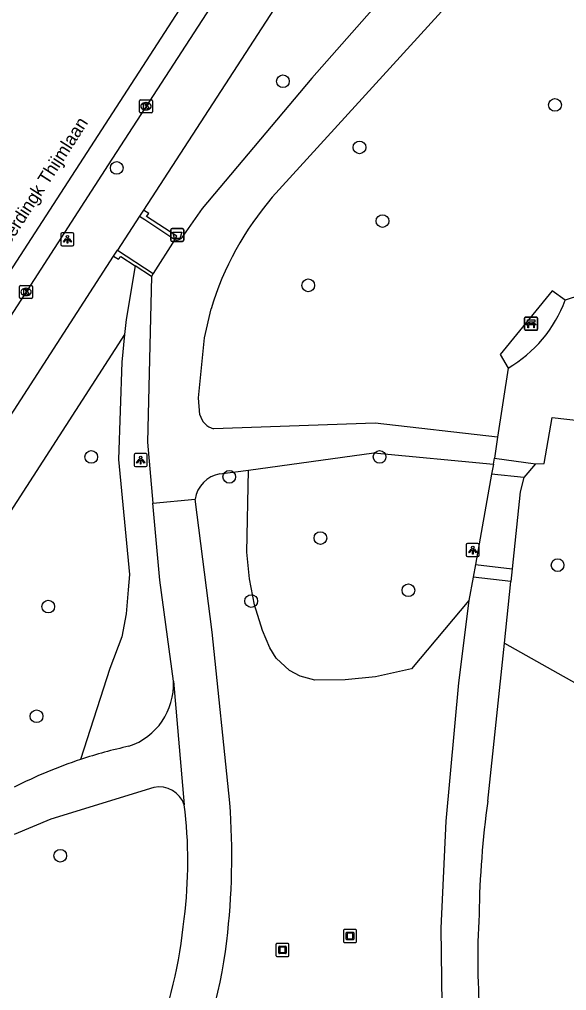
# Model space of a CAD drawing. Extents: x 161402 to 161933, y 381650 to 382313.
# Drawn here: x 161500.4 to 161542.5, y 381916.2 to 381991 of the extents above; entities that cross this region are included whole.
import ezdxf

# ---------------------------------------------------------------- set-up
doc = ezdxf.new("R2010")
doc.units = 0
for name, color, linetype in [('IMGEO_Afvalbak', 7, 'Continuous'), ('IMGEO_Bank', 7, 'Continuous'), ('IMGEO_Boom', 7, 'Continuous'), ('IMGEO_Groenvoorziening', 7, 'Continuous'), ('IMGEO_Kolk', 7, 'Continuous'), ('IMGEO_Kunstobject', 7, 'Continuous'), ('IMGEO_Lichtpunt', 7, 'Continuous'), ('IMGEO_Muur', 7, 'Continuous'), ('IMGEO_Openbare_ruimte_label', 7, 'Continuous'), ('IMGEO_Rijbaan_lokaal_gesloten', 7, 'Continuous'), ('IMGEO_Voetpad_gesloten', 7, 'Continuous'), ('IMGEO_Voetpad_open', 7, 'Continuous')]:
    doc.layers.add(name, color=color, linetype=linetype)

msp = doc.modelspace()

# ---------------------------------------------------------------- linework, layer by layer
at = {"layer": 'IMGEO_Afvalbak'}
for p, q in [((161512.056, 381973.98), (161512.056, 381974.78)), ((161512.056, 381974.78), (161512.056, 381973.98)), ((161512.156, 381974.88), (161512.946, 381974.88)), ((161512.946, 381974.88), (161512.156, 381974.88)), ((161513.046, 381974.78), (161513.046, 381973.98)), ((161513.046, 381973.98), (161513.046, 381974.78)), ((161512.946, 381973.88), (161512.156, 381973.88)), ((161512.156, 381973.88), (161512.946, 381973.88))]:
    msp.add_line(p, q, dxfattribs=at)
msp.add_lwpolyline([(161512.199, 381974.594), (161512.903, 381974.594), (161512.754, 381974.124), (161512.348, 381974.124), (161512.199, 381974.594)], dxfattribs=at)
for centre, start, end in [((161512.156, 381974.78), 90, 180), ((161512.156, 381974.78), 90, 180), ((161512.946, 381974.78), 0, 90), ((161512.946, 381974.78), 360, 90), ((161512.156, 381973.98), 180, 270), ((161512.156, 381973.98), 180, 270), ((161512.946, 381973.98), 270, 0), ((161512.946, 381973.98), 270, 0)]:
    msp.add_arc(centre, 0.1, start, end, dxfattribs=at)
at = {"layer": 'IMGEO_Bank'}
for p, q in [((161539.283, 381967.136), (161539.283, 381967.977)), ((161539.283, 381967.977), (161539.283, 381967.136)), ((161539.358, 381968.061), (161540.199, 381968.061)), ((161540.199, 381968.061), (161539.358, 381968.061)), ((161540.283, 381967.986), (161540.283, 381967.145)), ((161540.283, 381967.145), (161540.283, 381967.986)), ((161540.208, 381967.061), (161539.367, 381967.061)), ((161539.367, 381967.061), (161540.208, 381967.061)), ((161539.98, 381967.459), (161539.587, 381967.459)), ((161539.592, 381967.567), (161539.592, 381967.673)), ((161539.636, 381967.673), (161539.636, 381967.567)), ((161539.924, 381967.679), (161539.642, 381967.679)), ((161539.642, 381967.561), (161539.924, 381967.561)), ((161539.93, 381967.567), (161539.93, 381967.673)), ((161539.974, 381967.673), (161539.974, 381967.567))]:
    msp.add_line(p, q, dxfattribs=at)
for points in [[(161539.586, 381967.679), (161539.5, 381967.679), (161539.5, 381967.84), (161540.063, 381967.84), (161540.063, 381967.679), (161539.98, 381967.679)], [(161539.53, 381967.459), (161539.388, 381967.459), (161539.5, 381967.561), (161539.586, 381967.561)], [(161539.58, 381967.452), (161539.58, 381967.245), (161539.537, 381967.245), (161539.537, 381967.452)], [(161539.98, 381967.561), (161540.063, 381967.561), (161540.175, 381967.459), (161540.036, 381967.459)], [(161540.03, 381967.452), (161540.03, 381967.245), (161539.986, 381967.245), (161539.986, 381967.452)]]:
    msp.add_lwpolyline(points, dxfattribs=at)
for centre, radius, start, end in [((161539.361, 381967.983), 0.0779, 92.4484, 184.28452), ((161539.361, 381967.983), 0.0779, 92.4484, 184.28452), ((161540.205, 381967.983), 0.0779, 2.4484, 94.28452), ((161540.205, 381967.983), 0.0779, 2.4484, 94.28452), ((161539.361, 381967.139), 0.0779, 182.4484, 274.28452), ((161539.361, 381967.139), 0.0779, 182.4484, 274.28452), ((161539.53, 381967.452), 0.00671, 2.89567, 87.10433), ((161539.587, 381967.452), 0.00671, 92.89567, 177.10433), ((161539.585, 381967.672), 0.00671, 2.89567, 87.10433), ((161539.585, 381967.568), 0.00671, 272.89567, 357.10433), ((161539.642, 381967.672), 0.00671, 92.89567, 177.10433), ((161539.642, 381967.568), 0.00671, 182.89567, 267.10433), ((161539.924, 381967.672), 0.00671, 2.89567, 87.10433), ((161539.924, 381967.568), 0.00671, 272.89567, 357.10433), ((161539.981, 381967.672), 0.00671, 92.89567, 177.10433), ((161539.981, 381967.568), 0.00671, 182.89567, 267.10433), ((161539.979, 381967.452), 0.00671, 2.89567, 87.10433), ((161540.036, 381967.452), 0.00671, 92.89567, 177.10433), ((161540.205, 381967.139), 0.0779, 272.4484, 4.28452), ((161540.205, 381967.139), 0.0779, 272.4484, 4.28452)]:
    msp.add_arc(centre, radius, start, end, dxfattribs=at)
at = {"layer": 'IMGEO_Boom'}
for centre in [(161520.681, 381986.224), (161541.622, 381984.404), (161526.576, 381981.129), (161507.896, 381979.545), (161528.346, 381975.453), (161522.628, 381970.508), (161505.933, 381957.295), (161528.12, 381957.302), (161516.555, 381955.763), (161523.568, 381951.047), (161541.817, 381948.963), (161530.341, 381947.03), (161502.618, 381945.772), (161518.24, 381946.2), (161501.719, 381937.331), (161503.545, 381926.59)]:
    msp.add_circle(centre, 0.489, dxfattribs=at)
at = {"layer": 'IMGEO_Groenvoorziening'}
for points in [[(161509.308, 381972.015), (161508.618, 381967.87), (161508.501, 381966.732)], [(161508.501, 381966.732), (161469.767, 381906.69), (161463.799, 381897.019)], [(161508.501, 381966.732), (161508.281, 381964.587), (161508.029, 381957.094), (161508.87, 381948.254), (161508.777, 381947.074), (161508.622, 381945.207), (161508.281, 381943.455), (161507.356, 381941.013), (161505.105, 381933.996)], [(161534.991, 381946.237), (161530.572, 381940.988), (161527.811, 381940.367), (161525.479, 381940.12), (161523.133, 381940.118), (161522.019, 381940.405), (161521.193, 381940.842), (161520.168, 381941.793), (161519.671, 381942.584), (161519.118, 381943.929), (161518.506, 381945.898), (161518.104, 381947.92), (161517.916, 381949.973), (161518.029, 381956.285)], [(161537.726, 381942.964), (161546.992, 381937.737), (161549.718, 381935.374), (161552.345, 381934.301)]]:
    msp.add_lwpolyline(points, dxfattribs=at)
at = {"layer": 'IMGEO_Kolk'}
for p, q in [((161509.644, 381983.873), (161509.644, 381984.725)), ((161509.719, 381984.799), (161510.571, 381984.799)), ((161510.132, 381984.579), (161510.157, 381984.579)), ((161510.645, 381984.725), (161510.645, 381983.873)), ((161510.571, 381983.799), (161509.719, 381983.799)), ((161510.155, 381984.019), (161510.13, 381984.019)), ((161500.415, 381969.577), (161500.415, 381970.429)), ((161500.49, 381970.503), (161501.342, 381970.503)), ((161500.903, 381970.283), (161500.928, 381970.283)), ((161501.416, 381970.429), (161501.416, 381969.577)), ((161501.342, 381969.503), (161500.49, 381969.503)), ((161500.926, 381969.723), (161500.901, 381969.723))]:
    msp.add_line(p, q, dxfattribs=at)
for points in [[(161509.644, 381983.873), (161509.644, 381984.725)], [(161509.719, 381984.799), (161510.571, 381984.799)], [(161509.965, 381984.499), (161510.088, 381984.499), (161510.088, 381984.348), (161510.218, 381984.499), (161510.382, 381984.499), (161510.236, 381984.348), (161510.389, 381984.099), (161510.237, 381984.099), (161510.152, 381984.263), (161510.088, 381984.196), (161510.088, 381984.099), (161509.965, 381984.099), (161509.965, 381984.499)], [(161510.645, 381984.725), (161510.645, 381983.873)], [(161510.571, 381983.799), (161509.719, 381983.799)], [(161500.415, 381969.577), (161500.415, 381970.429)], [(161500.49, 381970.503), (161501.342, 381970.503)], [(161500.736, 381970.203), (161500.859, 381970.203), (161500.859, 381970.052), (161500.989, 381970.203), (161501.153, 381970.203), (161501.007, 381970.052), (161501.16, 381969.803), (161501.008, 381969.803), (161500.923, 381969.967), (161500.859, 381969.9), (161500.859, 381969.803), (161500.736, 381969.803), (161500.736, 381970.203)], [(161501.416, 381970.429), (161501.416, 381969.577)], [(161501.342, 381969.503), (161500.49, 381969.503)]]:
    msp.add_lwpolyline(points, dxfattribs=at)
for centre, start, end in [((161509.721, 381984.723), 91.55205, 178.44795), ((161509.721, 381984.723), 91.55205, 178.44795), ((161510.569, 381984.723), 1.55205, 88.44795), ((161510.569, 381984.723), 1.55205, 88.44795), ((161509.721, 381983.875), 181.55205, 268.44795), ((161509.721, 381983.875), 181.55205, 268.44795), ((161510.569, 381983.875), 271.55205, 358.44795), ((161510.569, 381983.875), 271.55205, 358.44795), ((161500.492, 381970.427), 91.55205, 178.44795), ((161500.492, 381970.427), 91.55205, 178.44795), ((161501.34, 381970.427), 1.55205, 88.44795), ((161501.34, 381970.427), 1.55205, 88.44795), ((161500.492, 381969.579), 181.55205, 268.44795), ((161500.492, 381969.579), 181.55205, 268.44795), ((161501.34, 381969.579), 271.55205, 358.44795), ((161501.34, 381969.579), 271.55205, 358.44795)]:
    msp.add_arc(centre, 0.0765, start, end, dxfattribs=at)
for centre, major_axis, ratio, start_param, end_param in [((161510.131, 381984.299), (-0.387, 0.002), 0.722429, 4.712389, 7.853982), ((161510.156, 381984.299), (-0.39, 0.002), 0.717154, 1.570796, 4.712389), ((161500.902, 381970.003), (-0.387, 0.002), 0.722429, 4.712389, 7.853982), ((161500.927, 381970.003), (-0.39, 0.002), 0.717154, 1.570796, 4.712389)]:
    msp.add_ellipse(centre, major_axis=major_axis, ratio=ratio, start_param=start_param, end_param=end_param, dxfattribs=at)
at = {"layer": 'IMGEO_Kunstobject'}
for p, q in [((161525.344, 381920.824), (161525.344, 381919.983)), ((161525.344, 381920.824), (161525.344, 381919.983)), ((161526.26, 381920.908), (161525.419, 381920.908)), ((161526.26, 381920.908), (161525.419, 381920.908)), ((161525.608, 381920.696), (161526.082, 381920.696)), ((161526.344, 381919.992), (161526.344, 381920.833)), ((161526.344, 381919.992), (161526.344, 381920.833)), ((161525.558, 381920.172), (161525.558, 381920.646)), ((161526.082, 381920.122), (161525.608, 381920.122)), ((161525.638, 381920.596), (161525.638, 381920.222)), ((161526.032, 381920.616), (161525.658, 381920.616)), ((161525.658, 381920.202), (161526.032, 381920.202)), ((161526.052, 381920.222), (161526.052, 381920.596)), ((161526.132, 381920.646), (161526.132, 381920.172)), ((161520.149, 381919.753), (161520.149, 381918.912)), ((161520.149, 381919.753), (161520.149, 381918.912)), ((161521.065, 381919.837), (161520.224, 381919.837)), ((161521.065, 381919.837), (161520.224, 381919.837)), ((161520.363, 381919.101), (161520.363, 381919.575)), ((161520.413, 381919.625), (161520.887, 381919.625)), ((161520.443, 381919.525), (161520.443, 381919.151)), ((161520.837, 381919.545), (161520.463, 381919.545)), ((161520.857, 381919.151), (161520.857, 381919.525)), ((161520.937, 381919.575), (161520.937, 381919.101)), ((161521.149, 381918.921), (161521.149, 381919.762)), ((161521.149, 381918.921), (161521.149, 381919.762)), ((161525.428, 381919.908), (161526.269, 381919.908)), ((161525.428, 381919.908), (161526.269, 381919.908)), ((161520.233, 381918.837), (161521.074, 381918.837)), ((161520.233, 381918.837), (161521.074, 381918.837)), ((161520.887, 381919.051), (161520.413, 381919.051)), ((161520.463, 381919.131), (161520.837, 381919.131))]:
    msp.add_line(p, q, dxfattribs=at)
for centre, radius, start, end in [((161525.422, 381920.83), 0.0779, 92.4484, 184.28452), ((161525.422, 381920.83), 0.0779, 92.4484, 184.28452), ((161525.608, 381920.646), 0.05, 90, 180), ((161526.082, 381920.646), 0.05, 360, 90), ((161526.266, 381920.83), 0.0779, 2.4484, 94.28452), ((161526.266, 381920.83), 0.0779, 2.4484, 94.28452), ((161525.422, 381919.986), 0.0779, 182.4484, 274.28452), ((161525.422, 381919.986), 0.0779, 182.4484, 274.28452), ((161525.608, 381920.172), 0.05, 180, 270), ((161525.658, 381920.596), 0.02, 90, 180), ((161525.658, 381920.222), 0.02, 180, 270), ((161526.032, 381920.596), 0.02, 360, 90), ((161526.032, 381920.222), 0.02, 270, 0), ((161526.082, 381920.172), 0.05, 270, 0), ((161526.266, 381919.986), 0.0779, 272.4484, 4.28452), ((161526.266, 381919.986), 0.0779, 272.4484, 4.28452), ((161520.227, 381919.759), 0.0779, 92.4484, 184.28452), ((161520.227, 381919.759), 0.0779, 92.4484, 184.28452), ((161520.413, 381919.575), 0.05, 90, 180), ((161520.463, 381919.525), 0.02, 90, 180), ((161520.837, 381919.525), 0.02, 360, 90), ((161520.887, 381919.575), 0.05, 360, 90), ((161521.071, 381919.759), 0.0779, 2.4484, 94.28452), ((161521.071, 381919.759), 0.0779, 2.4484, 94.28452), ((161520.227, 381918.915), 0.0779, 182.4484, 274.28452), ((161520.227, 381918.915), 0.0779, 182.4484, 274.28452), ((161520.413, 381919.101), 0.05, 180, 270), ((161520.463, 381919.151), 0.02, 180, 270), ((161520.837, 381919.151), 0.02, 270, 0), ((161520.887, 381919.101), 0.05, 270, 0), ((161521.071, 381918.915), 0.0779, 272.4484, 4.28452), ((161521.071, 381918.915), 0.0779, 272.4484, 4.28452)]:
    msp.add_arc(centre, radius, start, end, dxfattribs=at)
at = {"layer": 'IMGEO_Lichtpunt'}
for p, q in [((161504.5, 381974.55), (161503.692, 381974.55)), ((161504.5, 381974.55), (161503.692, 381974.55)), ((161503.598, 381974.455), (161503.598, 381973.648)), ((161503.598, 381974.455), (161503.598, 381973.648)), ((161504.594, 381973.648), (161504.594, 381974.455)), ((161504.594, 381973.648), (161504.594, 381974.455)), ((161503.692, 381973.554), (161504.5, 381973.554)), ((161503.692, 381973.554), (161504.5, 381973.554)), ((161509.237, 381957.453), (161509.237, 381956.646)), ((161509.237, 381957.453), (161509.237, 381956.646)), ((161510.139, 381957.548), (161509.331, 381957.548)), ((161510.139, 381957.548), (161509.331, 381957.548)), ((161510.233, 381956.646), (161510.233, 381957.453)), ((161510.233, 381956.646), (161510.233, 381957.453)), ((161509.331, 381956.552), (161510.139, 381956.552)), ((161509.331, 381956.552), (161510.139, 381956.552)), ((161535.693, 381950.622), (161534.885, 381950.622)), ((161535.693, 381950.622), (161534.885, 381950.622)), ((161534.791, 381950.527), (161534.791, 381949.72)), ((161534.791, 381950.527), (161534.791, 381949.72)), ((161535.787, 381949.72), (161535.787, 381950.527)), ((161535.787, 381949.72), (161535.787, 381950.527)), ((161534.885, 381949.626), (161535.693, 381949.626)), ((161534.885, 381949.626), (161535.693, 381949.626))]:
    msp.add_line(p, q, dxfattribs=at)
for points in [[(161503.972, 381974.119), (161504.011, 381974.091), (161503.823, 381973.829), (161503.785, 381973.856), (161503.972, 381974.119)], [(161504.074, 381974.071), (161504.121, 381974.071), (161504.121, 381973.749), (161504.074, 381973.749), (161504.074, 381974.071)], [(161504.184, 381974.091), (161504.222, 381974.118), (161504.409, 381973.856), (161504.37, 381973.828), (161504.184, 381974.091)], [(161509.611, 381957.117), (161509.65, 381957.089), (161509.462, 381956.827), (161509.424, 381956.854), (161509.611, 381957.117)], [(161509.713, 381957.069), (161509.76, 381957.069), (161509.76, 381956.747), (161509.713, 381956.747), (161509.713, 381957.069)], [(161509.823, 381957.089), (161509.861, 381957.116), (161510.048, 381956.854), (161510.009, 381956.826), (161509.823, 381957.089)], [(161535.165, 381950.191), (161535.204, 381950.163), (161535.016, 381949.901), (161534.978, 381949.928), (161535.165, 381950.191)], [(161535.267, 381950.143), (161535.314, 381950.143), (161535.314, 381949.821), (161535.267, 381949.821), (161535.267, 381950.143)], [(161535.377, 381950.163), (161535.415, 381950.19), (161535.602, 381949.928), (161535.563, 381949.9), (161535.377, 381950.163)]]:
    msp.add_lwpolyline(points, dxfattribs=at)
for centre in [(161504.097, 381974.253), (161509.736, 381957.251), (161535.29, 381950.325)]:
    msp.add_circle(centre, 0.0994, dxfattribs=at)
for centre, start, end in [((161503.692, 381974.455), 90, 180), ((161503.692, 381974.455), 90, 180), ((161504.5, 381974.455), 0, 90), ((161504.5, 381974.455), 0, 90), ((161503.692, 381973.648), 180, 270), ((161503.692, 381973.648), 180, 270), ((161504.5, 381973.648), 270, 0), ((161504.5, 381973.648), 270, 360), ((161509.331, 381957.453), 90, 180), ((161509.331, 381957.453), 90, 180), ((161510.139, 381957.453), 0, 90), ((161510.139, 381957.453), 0, 90), ((161509.331, 381956.646), 180, 270), ((161509.331, 381956.646), 180, 270), ((161510.139, 381956.646), 270, 0), ((161510.139, 381956.646), 270, 360), ((161534.885, 381950.527), 90, 180), ((161534.885, 381950.527), 90, 180), ((161535.693, 381950.527), 0, 90), ((161535.693, 381950.527), 0, 90), ((161534.885, 381949.72), 180, 270), ((161534.885, 381949.72), 180, 270), ((161535.693, 381949.72), 270, 0), ((161535.693, 381949.72), 270, 360)]:
    msp.add_arc(centre, 0.0946, start, end, dxfattribs=at)
at = {"layer": 'IMGEO_Muur'}
for points in [[(161509.956, 381976.304), (161509.806, 381976.073), (161509.648, 381975.83)], [(161512.354, 381974.043), (161512.522, 381974.297), (161510.195, 381975.805), (161510.352, 381976.047), (161509.956, 381976.304)], [(161509.648, 381975.83), (161510.055, 381975.566), (161512.354, 381974.043)], [(161507.649, 381972.745), (161507.953, 381973.214)], [(161507.953, 381973.214), (161510.709, 381971.428)], [(161507.649, 381972.745), (161508.017, 381972.531), (161508.198, 381972.739), (161509.308, 381972.015)], [(161510.563, 381971.196), (161509.308, 381972.015)], [(161510.709, 381971.428), (161510.563, 381971.196)]]:
    msp.add_lwpolyline(points, dxfattribs=at)
at = {"layer": 'IMGEO_Rijbaan_lokaal_gesloten'}
for points in [[(161497.581, 381968.358), (161530.425, 382019.12)], [(161532.049, 382018.061), (161507.226, 381979.8), (161499.199, 381967.336)]]:
    msp.add_lwpolyline(points, dxfattribs=at)
at = {"layer": 'IMGEO_Voetpad_gesloten'}
for points in [[(161566.397, 382035.429), (161550.139, 382016.903), (161534.836, 382000), (161522.917, 381986.45), (161514.478, 381976.419), (161513.027, 381974.379)], [(161519.862, 381977.295), (161539.026, 381998.34)], [(161512.354, 381974.043), (161510.709, 381971.428)], [(161510.563, 381971.196), (161510.253, 381958.443), (161510.676, 381953.741)], [(161547.271, 381970.949), (161542.413, 381969.37)], [(161540.125, 381956.77), (161540.786, 381956.788), (161541.397, 381960.342), (161546.372, 381959.762), (161548.185, 381962.019), (161546.989, 381965.845), (161550.378, 381967.202), (161550.41, 381969.161), (161551.511, 381969.577)], [(161514.294, 381960.547), (161514.174, 381961.84), (161514.646, 381966.471), (161515.15, 381968.709)], [(161538.012, 381964.131), (161537.2, 381958.819)], [(161537.2, 381958.819), (161527.77, 381959.887), (161515.352, 381959.463)], [(161537.2, 381958.819), (161536.954, 381957.199)], [(161518.029, 381956.285), (161527.675, 381957.619), (161536.884, 381956.742)], [(161536.884, 381956.742), (161536.954, 381957.199)], [(161536.954, 381957.199), (161540.125, 381956.77)], [(161515.84, 381955.982), (161518.029, 381956.285)], [(161510.676, 381953.741), (161513.937, 381954.035)], [(161512.254, 381940.023), (161511.211, 381947.806), (161510.676, 381953.741)], [(161516.591, 381930.663), (161515.234, 381943.813), (161513.937, 381954.035)], [(161535.316, 381948.041), (161534.991, 381946.237)], [(161538.225, 381947.701), (161535.316, 381948.041)], [(161537.726, 381942.964), (161538.225, 381947.701)], [(161534.991, 381946.237), (161534.202, 381939.899), (161533.225, 381929.262), (161532.824, 381921.008), (161532.917, 381915.131), (161533.668, 381906.095)], [(161536.445, 381930.791), (161537.726, 381942.964)], [(161512.254, 381940.023), (161513.094, 381930.503)], [(161510.75, 381931.838), (161502.828, 381929.398), (161500, 381928.211)]]:
    msp.add_lwpolyline(points, dxfattribs=at)
for centre, radius, start, end in [((161538.145, 381961.675), 24.046, 139.49162, 162.99238), ((161512.522, 381974.549), 0.533, 251.63031, 341.43166), ((161532.889, 381972.903), 10.159, 300.28811, 339.64829), ((161515.722, 381960.882), 1.466, 193.20622, 255.40291), ((161516.156, 381953.77), 2.235, 98.12568, 173.18388), ((161507.248, 381939.774), 5.012, 288.4124, 2.8499), ((161516.698, 381899.034), 36.834, 102.33201, 108.34471), ((161516.832, 381898.676), 37.216, 108.36728, 116.88998), ((161511.184, 381929.875), 2.011, 18.20492, 102.46866), ((161478.123, 381926.149), 35.241, 352.81134, 7.09713), ((161462.665, 381926.529), 54.085, 353.07761, 4.38421), ((161607.713, 381920.964), 71.942, 172.14903, 179.12783), ((161474.949, 381925.549), 38.328, 338.97877, 354.29548), ((161593.932, 381918.633), 58.254, 176.62791, 184.85326), ((161478.809, 381924.445), 37.807, 333.93882, 353.26375)]:
    msp.add_arc(centre, radius, start, end, dxfattribs=at)
at = {"layer": 'IMGEO_Voetpad_open'}
for points in [[(161566.628, 382063.688), (161525.324, 382000), (161509.956, 381976.304)], [(161509.648, 381975.83), (161507.953, 381973.214)], [(161460.416, 381899.153), (161466.384, 381908.825), (161499.565, 381960.223), (161500, 381960.897), (161507.649, 381972.745)], [(161542.413, 381969.37), (161541.408, 381970.096), (161537.399, 381965.184), (161538.012, 381964.131)], [(161536.884, 381956.742), (161536.744, 381955.964)], [(161540.125, 381956.77), (161539.224, 381955.724)], [(161536.744, 381955.964), (161535.492, 381949.019)], [(161539.224, 381955.724), (161536.744, 381955.964)], [(161539.224, 381955.724), (161538.953, 381954.621), (161538.329, 381948.69)], [(161535.492, 381949.019), (161535.316, 381948.041)], [(161535.492, 381949.019), (161538.329, 381948.69)], [(161538.329, 381948.69), (161538.225, 381947.701)]]:
    msp.add_lwpolyline(points, dxfattribs=at)

# ---------------------------------------------------------------- texts
at = {"layer": 'IMGEO_Openbare_ruimte_label'}
msp.add_text('Alberdingk Thijmlaan', height=1, rotation=57.24756, dxfattribs=at).set_placement((161498.973, 381972.542))

doc.saveas('drawing.dxf')
